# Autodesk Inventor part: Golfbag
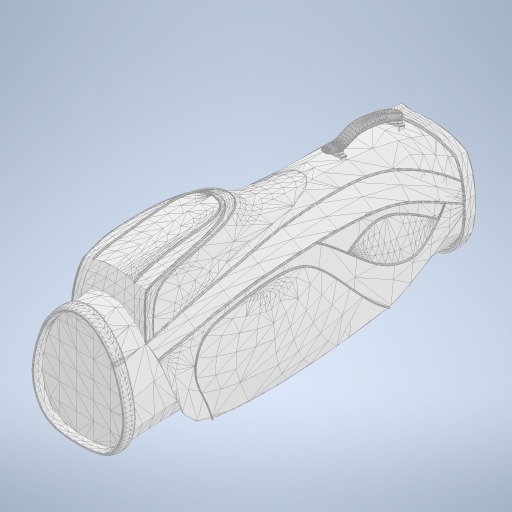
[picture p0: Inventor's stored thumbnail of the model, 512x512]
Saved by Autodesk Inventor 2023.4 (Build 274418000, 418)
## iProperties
Created: 2025-03
Part Number: Golfbag
Material: Générique
Document SubType Name: Modeling
Designer: bruno
Density: 1 g/cm^3
Appearance: Par défaut
Author: bruno
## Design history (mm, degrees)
node "Golfbag_2017_2"
  node "FonctionMaillage1"
